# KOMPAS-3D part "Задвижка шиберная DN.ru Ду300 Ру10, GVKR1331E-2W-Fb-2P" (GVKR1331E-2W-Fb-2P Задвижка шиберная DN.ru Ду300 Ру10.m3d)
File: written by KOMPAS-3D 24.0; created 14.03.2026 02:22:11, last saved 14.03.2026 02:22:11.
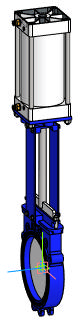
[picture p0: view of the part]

Document properties: Автор: DN.RU; Полное имя файла: D:\PROJECT CAD\DN.RU\...192.(ACTUALE) GVKR1331E-2W-Fb-2P Задвижка шиберная DN.ru Ру6-10\DN300_PN10\GVKR1331E-2W-Fb-2P Задвижка шиберная DN.ru Ду300 Ру10.m3d

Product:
- Body: Твердое тело1  | qty 1
    Масса: 198.39415
- Part/product: Задвижка шиберная DN.ru Ду300 Ру10  | designation GVKR1331E-2W-Fb-2P
    Масса: 75
    Раздел спецификации: Прочие изделия
    Комментарий: D040-07405
    Примечание: D040-07405
    additional columns: Чугун, серый

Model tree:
1. Твердое тело1  (labels: Твердое тело1)

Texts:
  GVKR1331E-2W-Fb-2P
